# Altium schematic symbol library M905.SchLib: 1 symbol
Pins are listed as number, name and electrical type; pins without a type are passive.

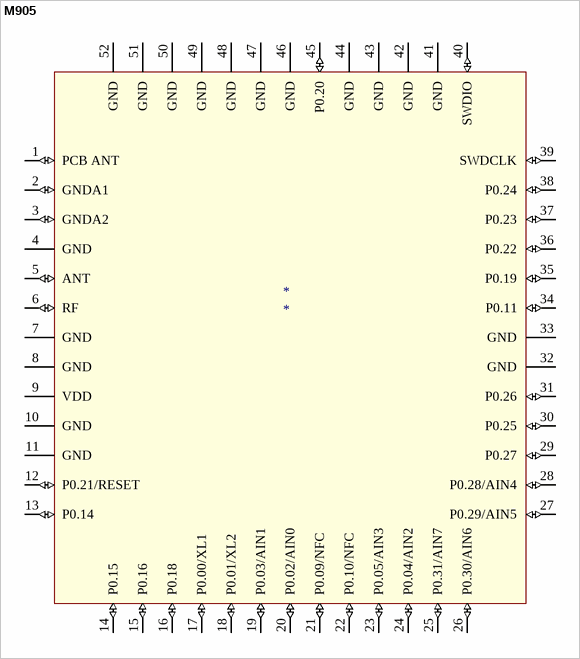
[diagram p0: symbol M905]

## M905
designator *
footprint M905_Pinout_48P
pins: 1 PCB ANT (io), 2 GNDA1 (io), 3 GNDA2 (io), 4 GND (power), 5 ANT (io), 6 RF (io), 7 GND (power), 8 GND (power), 9 VDD (power), 10 GND (power), 11 GND (power), 12 P0.21/RESET (io), 13 P0.14 (io), 14 P0.15 (io), 15 P0.16 (io), 16 P0.18 (io), 17 P0.00/XL1 (io), 18 P0.01/XL2 (io), 19 P0.03/AIN1 (io), 20 P0.02/AIN0 (io), 21 P0.09/NFC (io), 22 P0.10/NFC (io), 23 P0.05/AIN3 (io), 24 P0.04/AIN2 (io), 25 P0.31/AIN7 (io), 26 P0.30/AIN6 (io), 27 P0.29/AIN5 (io), 28 P0.28/AIN4 (io), 29 P0.27 (io), 30 P0.25 (io), 31 P0.26 (io), 32 GND (power), 33 GND (power), 34 P0.11 (io), 35 P0.19 (io), 36 P0.22 (io), 37 P0.23 (io), 38 P0.24 (io), 39 SWDCLK (io), 40 SWDIO (io), 41 GND (power), 42 GND (power), 43 GND (power), 44 GND (power), 45 P0.20 (io), 46 GND (power), 47 GND (power), 48 GND (power), 49 GND (power), 50 GND (power), 51 GND (power), 52 GND (power)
